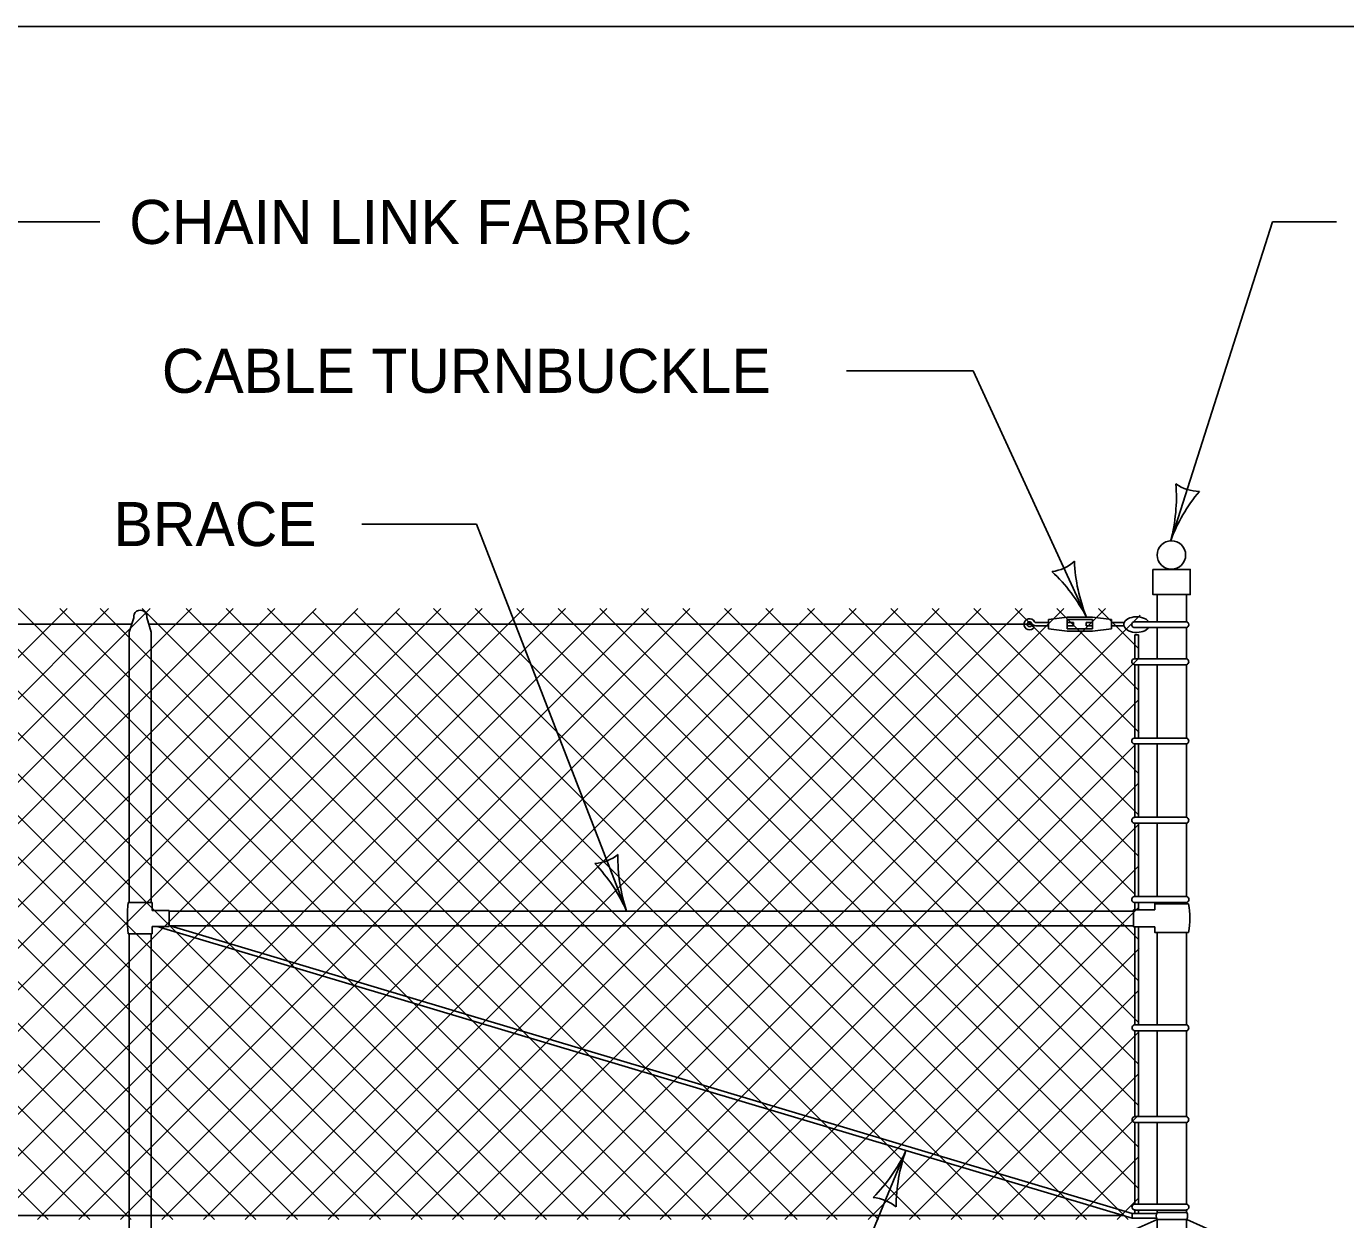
# Model space of a CAD drawing. Extents: x 49973.1 to 50021, y 49987.6 to 50015.4.
# Drawn here: x 50003.121 to 50004.917, y 49997.374 to 49998.999 of the extents above; entities that cross this region are included whole.
import ezdxf

# ---------------------------------------------------------------- set-up
doc = ezdxf.new("R2010")
doc.units = 0
for name, color, linetype in [('Level 1', 7, 'Continuous'), ('Level 2', 7, 'Continuous'), ('Level 3', 7, 'Continuous')]:
    doc.layers.add(name, color=color, linetype=linetype)

msp = doc.modelspace()

# ---------------------------------------------------------------- linework, layer by layer
at = {"layer": 'Level 1'}
for p, q in [((50004.6608, 49998.2252), (50004.6608, 49998.1883)), ((50004.7008, 49998.2252), (50004.7008, 49998.1883)), ((50002.3178, 49998.2062), (50003.1504, 49997.3738)), ((50002.3437, 49997.3738), (50003.1761, 49998.2062)), ((50002.3741, 49998.2062), (50003.207, 49997.3738)), ((50002.4003, 49997.3738), (50003.2327, 49998.2062)), ((50002.431, 49998.2062), (50003.2636, 49997.3738)), ((50002.4567, 49997.3738), (50003.2891, 49998.2062)), ((50002.4876, 49998.2062), (50003.3202, 49997.3738)), ((50002.5133, 49997.3738), (50003.3457, 49998.2062)), ((50002.5441, 49998.2062), (50003.3768, 49997.3738)), ((50002.5699, 49997.3738), (50003.4023, 49998.2062)), ((50002.6006, 49998.2062), (50003.4332, 49997.3738)), ((50002.6265, 49997.3738), (50003.4589, 49998.2062)), ((50002.6574, 49998.2062), (50003.4898, 49997.3738)), ((50002.6831, 49997.3738), (50003.5155, 49998.2062)), ((50002.7139, 49998.2062), (50003.5464, 49997.3738)), ((50002.7397, 49997.3738), (50003.5721, 49998.2062)), ((50002.7705, 49998.2062), (50003.603, 49997.3738)), ((50002.7963, 49997.3738), (50003.6287, 49998.2062)), ((50002.8271, 49998.2062), (50003.6596, 49997.3738)), ((50002.8527, 49997.3738), (50003.6851, 49998.2062)), ((50002.8837, 49998.2062), (50003.7162, 49997.3738)), ((50002.9093, 49997.3738), (50003.7417, 49998.2062)), ((50002.9401, 49998.2062), (50003.7726, 49997.3738)), ((50002.9659, 49997.3738), (50003.7983, 49998.2062)), ((50002.9967, 49998.2062), (50003.8292, 49997.3738)), ((50003.0225, 49997.3738), (50003.8549, 49998.2062)), ((50003.0533, 49998.2062), (50003.8858, 49997.3738)), ((50003.0791, 49997.3738), (50003.9115, 49998.2062)), ((50003.1099, 49998.2062), (50003.9424, 49997.3738)), ((50003.1357, 49997.3738), (50003.9681, 49998.2062)), ((50003.1665, 49998.2062), (50003.999, 49997.3738)), ((50003.1921, 49997.3738), (50004.0245, 49998.2062)), ((50003.2211, 49998.2062), (50004.0534, 49997.3738)), ((50003.2488, 49997.3739), (50004.0811, 49998.2062)), ((50003.2608, 49998.1741), (50003.2671, 49998.1936)), ((50003.2785, 49998.2062), (50004.1105, 49997.3738)), ((50003.2908, 49998.1741), (50003.2848, 49998.1939)), ((50003.3054, 49997.3739), (50004.1377, 49998.2062)), ((50003.3385, 49998.2062), (50004.1706, 49997.3738)), ((50003.3619, 49997.3738), (50004.1943, 49998.2062)), ((50003.3927, 49998.2062), (50004.225, 49997.3738)), ((50003.4185, 49997.3738), (50004.2509, 49998.2062)), ((50003.4493, 49998.2062), (50004.2811, 49997.3738)), ((50003.4751, 49997.3738), (50004.3075, 49998.2062)), ((50003.5107, 49998.2014), (50004.3381, 49997.3738)), ((50003.5317, 49997.3738), (50004.3641, 49998.2062)), ((50003.5673, 49998.2014), (50004.3947, 49997.3738)), ((50003.5881, 49997.3738), (50004.4205, 49998.2062)), ((50003.6239, 49998.2014), (50004.4509, 49997.3738)), ((50003.6447, 49997.3738), (50004.4771, 49998.2062)), ((50003.675, 49998.2062), (50004.508, 49997.3738)), ((50003.7013, 49997.3738), (50004.5337, 49998.2062)), ((50003.7318, 49998.2062), (50004.5645, 49997.3738)), ((50003.7579, 49997.3738), (50004.5903, 49998.2062)), ((50003.7885, 49998.2062), (50004.6212, 49997.3738)), ((50003.8143, 49997.3738), (50004.6378, 49998.1973)), ((50003.8452, 49998.2062), (50004.6357, 49997.4159)), ((50003.9017, 49998.2062), (50004.6355, 49997.4727)), ((50003.9583, 49998.2062), (50004.6355, 49997.5292)), ((50004.0148, 49998.2062), (50004.6359, 49997.5852)), ((50004.0716, 49998.2062), (50004.636, 49997.6418)), ((50004.128, 49998.2062), (50004.6357, 49997.6986)), ((50004.1847, 49998.2062), (50004.6354, 49997.7556)), ((50004.2413, 49998.2062), (50004.6299, 49997.8177)), ((50004.2979, 49998.2062), (50004.6356, 49997.8685)), ((50004.3545, 49998.2062), (50004.6354, 49997.9253)), ((50004.4109, 49998.2062), (50004.636, 49997.9811)), ((50004.4675, 49998.2062), (50004.6364, 49998.0374)), ((50004.5384, 49998.1945), (50004.5127, 49998.1913)), ((50004.5241, 49998.2062), (50004.6352, 49998.0952)), ((50004.5727, 49998.1945), (50004.5384, 49998.1945)), ((50004.5985, 49998.1913), (50004.5727, 49998.1945)), ((50004.5807, 49998.2062), (50004.6358, 49998.1512)), ((50001.8875, 49998.1849), (50003.2643, 49998.1849)), ((50003.2875, 49998.1849), (50004.4889, 49998.1849)), ((50004.4897, 49998.1832), (50004.4934, 49998.181)), ((50004.4956, 49998.187), (50004.5127, 49998.187)), ((50004.4956, 49998.1827), (50004.5127, 49998.1827)), ((50004.5127, 49998.1784), (50004.5127, 49998.1913)), ((50004.5127, 49998.1784), (50004.5384, 49998.1752)), ((50004.5727, 49998.1913), (50004.5384, 49998.1913)), ((50004.5384, 49998.1784), (50004.5384, 49998.1913)), ((50004.5384, 49998.187), (50004.547, 49998.187)), ((50004.5384, 49998.1827), (50004.547, 49998.1827)), ((50004.5727, 49998.1784), (50004.5384, 49998.1784)), ((50004.547, 49998.1827), (50004.547, 49998.187)), ((50004.5641, 49998.1827), (50004.5641, 49998.187)), ((50004.5727, 49998.187), (50004.5641, 49998.187)), ((50004.5727, 49998.1827), (50004.5641, 49998.1827)), ((50004.5727, 49998.1784), (50004.5727, 49998.1913)), ((50004.5727, 49998.1752), (50004.5985, 49998.1784)), ((50004.5985, 49998.1784), (50004.5985, 49998.1913)), ((50004.6158, 49998.187), (50004.5985, 49998.187)), ((50004.6155, 49998.1827), (50004.5985, 49998.1827)), ((50004.6302, 49998.1883), (50004.7008, 49998.1883)), ((50004.6302, 49998.1802), (50004.7006, 49998.1802)), ((50004.6608, 49998.1802), (50004.6608, 49998.1378)), ((50004.7008, 49998.1802), (50004.7008, 49998.1378)), ((50003.2608, 49998.1741), (50003.2608, 49997.8059)), ((50003.2908, 49998.1741), (50003.2908, 49997.8059)), ((50004.5727, 49998.1752), (50004.5384, 49998.1752)), ((50004.6302, 49998.1704), (50004.6352, 49998.1704)), ((50004.6302, 49998.1704), (50004.6302, 49998.1378)), ((50004.6352, 49998.1704), (50004.6352, 49998.1512)), ((50004.6352, 49998.1637), (50004.6352, 49998.1509)), ((50004.6352, 49998.1509), (50004.6352, 49998.1378)), ((50003.8709, 49997.3738), (50004.6348, 49998.1377)), ((50004.6302, 49998.1297), (50004.6302, 49998.0298)), ((50004.6303, 49998.1378), (50004.7008, 49998.1378)), ((50004.6304, 49998.1297), (50004.7006, 49998.1297)), ((50004.6352, 49998.1297), (50004.6352, 49998.0298)), ((50004.6608, 49998.1297), (50004.6608, 49998.0298)), ((50004.7008, 49998.1298), (50004.7008, 49998.0298)), ((50003.9275, 49997.3738), (50004.6345, 49998.0808)), ((50003.9841, 49997.3738), (50004.6308, 49998.0205)), ((50004.6302, 49998.0217), (50004.6302, 49997.9218)), ((50004.6303, 49998.0298), (50004.7008, 49998.0298)), ((50004.6304, 49998.0217), (50004.7006, 49998.0217)), ((50004.6352, 49998.0217), (50004.6352, 49997.9218)), ((50004.6608, 49998.0217), (50004.6608, 49997.9218)), ((50004.7008, 49998.0218), (50004.7008, 49997.9218)), ((50004.0407, 49997.3738), (50004.6354, 49997.9685)), ((50004.0974, 49997.3739), (50004.6349, 49997.9114)), ((50004.6302, 49997.9137), (50004.6302, 49997.8138)), ((50004.6303, 49997.9218), (50004.7008, 49997.9218)), ((50004.6304, 49997.9137), (50004.7006, 49997.9137)), ((50004.6352, 49997.9137), (50004.6352, 49997.8138)), ((50004.6608, 49997.9137), (50004.6608, 49997.8138)), ((50004.7008, 49997.9138), (50004.7008, 49997.8138)), ((50004.1538, 49997.3739), (50004.6358, 49997.8559)), ((50003.2592, 49997.8059), (50003.292, 49997.8059)), ((50003.292, 49997.8059), (50003.292, 49997.7951)), ((50004.2104, 49997.3739), (50004.6348, 49997.7983)), ((50004.6302, 49997.8057), (50004.6302, 49997.7956)), ((50004.6303, 49997.8138), (50004.7011, 49997.8138)), ((50004.6304, 49997.8057), (50004.6997, 49997.8057)), ((50004.6352, 49997.8057), (50004.6352, 49997.7956)), ((50004.6608, 49997.8057), (50004.6608, 49997.804)), ((50004.7008, 49997.8059), (50004.7008, 49997.804)), ((50003.292, 49997.7951), (50003.3152, 49997.7951)), ((50003.3152, 49997.773), (50003.3152, 49997.7951)), ((50003.3152, 49997.7941), (50004.6287, 49997.7941)), ((50004.6287, 49997.7956), (50004.6576, 49997.7956)), ((50004.6287, 49997.7727), (50004.6287, 49997.7956)), ((50003.2592, 49997.7633), (50003.2922, 49997.7633)), ((50003.2608, 49997.7633), (50003.2608, 49997.3739)), ((50003.2908, 49997.7633), (50003.2908, 49997.3739)), ((50003.2922, 49997.7633), (50003.2922, 49997.773)), ((50003.2922, 49997.773), (50003.3152, 49997.773)), ((50004.6267, 49997.3756), (50003.2988, 49997.773)), ((50003.3152, 49997.7741), (50004.6287, 49997.7741)), ((50004.6267, 49997.382), (50003.3164, 49997.7741)), ((50004.6287, 49997.7727), (50004.6576, 49997.7727)), ((50004.6302, 49997.7727), (50004.6302, 49997.6391)), ((50004.6352, 49997.7727), (50004.6352, 49997.6391)), ((50004.6608, 49997.765), (50004.6608, 49997.6391)), ((50004.7008, 49997.765), (50004.7008, 49997.6391)), ((50004.267, 49997.3739), (50004.6361, 49997.743)), ((50004.3236, 49997.3739), (50004.6351, 49997.6854)), ((50004.6305, 49997.6391), (50004.7008, 49997.6391)), ((50004.3802, 49997.3739), (50004.6348, 49997.6285)), ((50004.6302, 49997.631), (50004.6302, 49997.5141)), ((50004.6309, 49997.631), (50004.7006, 49997.631)), ((50004.6352, 49997.631), (50004.6352, 49997.5271)), ((50004.6608, 49997.631), (50004.6608, 49997.5141)), ((50004.7008, 49997.6311), (50004.7008, 49997.5141)), ((50004.4368, 49997.3739), (50004.6349, 49997.572)), ((50004.4932, 49997.3739), (50004.6345, 49997.5152)), ((50004.6305, 49997.5141), (50004.7008, 49997.5141)), ((50004.6352, 49997.5271), (50004.6352, 49997.5141)), ((50004.6302, 49997.506), (50004.6302, 49997.395)), ((50004.6309, 49997.506), (50004.7006, 49997.506)), ((50004.6352, 49997.506), (50004.6352, 49997.395)), ((50004.6608, 49997.506), (50004.6608, 49997.395)), ((50004.7008, 49997.5061), (50004.7008, 49997.395)), ((50004.5498, 49997.3739), (50004.6348, 49997.4589)), ((50004.6063, 49997.3738), (50004.636, 49997.4035)), ((50004.6302, 49997.3869), (50004.6302, 49997.382)), ((50004.6306, 49997.395), (50004.7009, 49997.395)), ((50004.6307, 49997.3869), (50004.7007, 49997.3869)), ((50004.6352, 49997.3869), (50004.6352, 49997.382)), ((50004.6608, 49997.3869), (50004.6608, 49997.3836)), ((50004.7008, 49997.387), (50004.7008, 49997.3836)), ((50001.6211, 49997.3795), (50004.6137, 49997.3795)), ((50003.2608, 49997.3739), (50003.2608, 49996.9341)), ((50003.2908, 49997.3739), (50003.2908, 49996.9341)), ((50004.6158, 49997.3541), (50004.6607, 49997.3741)), ((50004.6267, 49997.3756), (50004.6267, 49997.382)), ((50004.6599, 49997.382), (50004.6267, 49997.382)), ((50004.66, 49997.3756), (50004.6267, 49997.3756)), ((50004.6607, 49997.3836), (50004.7011, 49997.3836)), ((50004.6607, 49997.3741), (50004.7011, 49997.3741)), ((50004.6608, 49997.3741), (50004.6608, 49996.9341)), ((50004.7008, 49997.3741), (50004.7008, 49996.9341)), ((50004.7458, 49997.3541), (50004.7011, 49997.3741))]:
    msp.add_line(p, q, dxfattribs=at)
for points in [[(49999.3835, 49998.9992), (50016.7501, 49998.9992), (50016.7501, 49987.7988), (49999.3835, 49987.7988)], [(50004.6549, 49998.2595), (50004.6549, 49998.2252), (50004.7058, 49998.2252), (50004.7058, 49998.2595)]]:
    msp.add_lwpolyline(points, close=True, dxfattribs=at)
for points in [[(50004.7035, 49997.804), (50004.6576, 49997.804), (50004.6576, 49997.7956)], [(50004.6576, 49997.7727), (50004.6576, 49997.765), (50004.7035, 49997.765)]]:
    msp.add_lwpolyline(points, dxfattribs=at)
msp.add_circle((50004.6802, 49998.2791), 0.0194, dxfattribs=at)
for centre, radius, start, end in [((50003.2759, 49998.1951), 0.00895, 352.3754, 189.572), ((50004.4869, 49998.1848), 0.00749, 26.3878, 329.065), ((50004.4869, 49998.1848), 0.00321, 26.3878, 329.7343), ((50004.4956, 49998.1891), 0.00642, 206.3878, 270), ((50004.4956, 49998.1891), 0.00214, 206.3878, 270), ((50004.6302, 49998.1842), 0.00405, 89.5405, 270.6652), ((50004.6997, 49998.1843), 0.00417, 282.5816, 75.1527), ((50004.6302, 49998.1338), 0.00405, 87.9212, 273.176), ((50004.6997, 49998.1338), 0.00417, 282.5816, 75.1527), ((50004.6302, 49998.0258), 0.00405, 87.9212, 273.176), ((50004.6997, 49998.0258), 0.00417, 282.5816, 75.1527), ((50004.6302, 49997.9178), 0.00405, 87.9212, 269.2509), ((50004.6302, 49997.9178), 0.00405, 269.2509, 273.176), ((50004.6997, 49997.9178), 0.00417, 282.5816, 75.1527), ((50003.5104, 49997.7846), 0.2521, 175.1522, 184.845), ((50004.6302, 49997.8098), 0.00405, 87.9212, 273.176), ((50004.6997, 49997.8099), 0.00417, 269.5529, 70.4979), ((50004.599, 49997.7845), 0.1063, 349.4342, 10.5703), ((50004.6307, 49997.6351), 0.00405, 87.9212, 273.176), ((50004.6997, 49997.6351), 0.00417, 282.5816, 75.1527), ((50004.6307, 49997.5101), 0.00405, 92.0788, 273.176), ((50004.6997, 49997.5101), 0.00417, 282.5816, 75.1527), ((50004.6305, 49997.391), 0.00405, 87.9212, 273.176), ((50004.6998, 49997.391), 0.00417, 282.5816, 75.1527), ((50004.6687, 49997.3789), 0.00931, 149.3804, 210.7326), ((50004.6924, 49997.3789), 0.00992, 331.4429, 28.6748)]:
    msp.add_arc(centre, radius, start, end, dxfattribs=at)
for start_param, end_param in [(3.539885, 7.710522), (1.427337, 2.761839)]:
    msp.add_ellipse((50004.6328, 49998.1843), major_axis=(-0.0175, 0.0001), ratio=0.610393, start_param=start_param, end_param=end_param, dxfattribs=at)
at = {"layer": 'Level 3'}
for p, q in [((50003.1019, 49998.7328), (50003.2208, 49998.7328)), ((50004.6792, 49998.2985), (50004.8178, 49998.7328)), ((50004.9051, 49998.7328), (50004.8178, 49998.7328)), ((50004.4101, 49998.53), (50004.2376, 49998.53)), ((50004.5646, 49998.1945), (50004.4101, 49998.53)), ((50003.7339, 49998.3213), (50003.5776, 49998.3213)), ((50003.9382, 49997.7941), (50003.7339, 49998.3213)), ((50004.3186, 49997.4678), (50004.221, 49997.2308))]:
    msp.add_line(p, q, dxfattribs=at)
for centre, radius, start, end in [((50004.454, 49998.3582), 0.233, 345.1347, 4.3845), ((50004.7182, 49998.4206), 0.0548, 234.4462, 270.1685), ((50004.888, 49998.2222), 0.2223, 139.7634, 159.9469), ((50004.5111, 49998.311), 0.0548, 276.8211, 312.5434), ((50004.7703, 49998.2789), 0.2223, 182.1383, 202.3218), ((50004.3579, 49998.0868), 0.233, 27.5096, 46.7594), ((50003.8918, 49997.9136), 0.0548, 273.3757, 309.0981), ((50004.1486, 49997.8661), 0.2223, 178.6929, 198.8764), ((50003.7255, 49997.6991), 0.233, 24.0642, 43.3141), ((50004.1168, 49997.5611), 0.2223, 315.0054, 335.1889), ((50004.5381, 49997.3896), 0.233, 160.3767, 179.6266), ((50004.2696, 49997.3493), 0.0548, 49.6882, 85.4106)]:
    msp.add_arc(centre, radius, start, end, dxfattribs=at)

# ---------------------------------------------------------------- texts
at = {"layer": 'Level 2'}
for s, p in [('CHAIN LINK FABRIC', (50003.2608, 49998.7028)), ('CABLE TURNBUCKLE', (50003.3052, 49998.5)), ('BRACE', (50003.2396, 49998.2913))]:
    msp.add_text(s, height=0.06, dxfattribs=at).set_placement(p)

doc.saveas('drawing.dxf')
